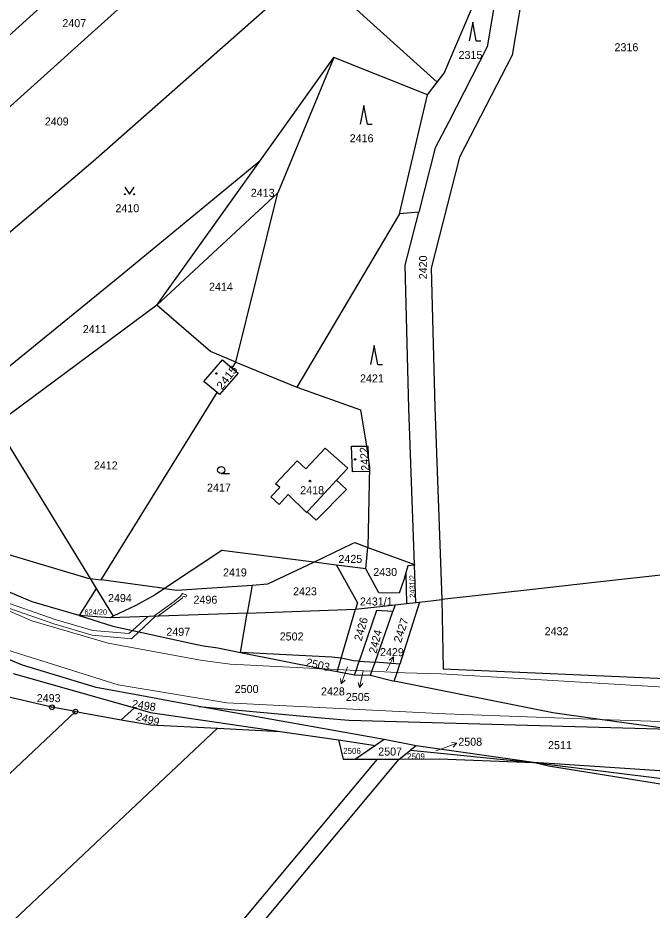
# Model space of a CAD drawing. Extents: x -606517 to -602431, y -1183120 to -1179397.
# Drawn here: x -604828.2 to -604693.5, y -1181046.7 to -1180857.3 of the extents above; entities that cross this region are included whole.
import ezdxf
from ezdxf.enums import TextEntityAlignment as Align

# ---------------------------------------------------------------- set-up
doc = ezdxf.new("R2010")
doc.units = 0
doc.header["$LTSCALE"] = 0.68
for name, color, linetype, lineweight in [('1', 7, 'Continuous', 25), ('13', 7, 'Continuous', 13), ('3', 7, 'Continuous', 25), ('4', 7, 'Continuous', 13), ('5', 7, 'Continuous', 25), ('7', 7, 'Continuous', 13), ('8', 7, 'Continuous', 25)]:
    doc.layers.add(name, color=color, linetype=linetype, lineweight=lineweight)
doc.layers.add('2', color=7, linetype='Continuous')

msp = doc.modelspace()

# ---------------------------------------------------------------- linework, layer by layer
at = {"layer": '1'}
for p, q in [((-604883.82, -1180909.45), (-604798.46, -1180832.55)), ((-604874.53, -1180916.36), (-604790.07, -1180840.29)), ((-604766.15, -1180846.54), (-604739.14, -1180870.96)), ((-604737.64, -1180869.05), (-604730.74, -1180852.82)), ((-604726.66, -1180852.57), (-604728.49, -1180863.44)), ((-604720.96, -1180851.82), (-604723.21, -1180865.2)), ((-604774.54, -1180854.61), (-604812.16, -1180887.79)), ((-604728.49, -1180863.44), (-604736.69, -1180879.34)), ((-604776.79, -1180887.7), (-604761.08, -1180865.73)), ((-604761.08, -1180865.73), (-604772.99, -1180894.46)), ((-604741.21, -1180873.62), (-604761.08, -1180865.73)), ((-604723.21, -1180865.2), (-604734.38, -1180886.88)), ((-604739.14, -1180870.96), (-604737.64, -1180869.05)), ((-604741.21, -1180873.62), (-604739.14, -1180870.96)), ((-604747.14, -1180898.88), (-604741.21, -1180873.62)), ((-604736.69, -1180879.34), (-604739.56, -1180884.92)), ((-604739.56, -1180884.92), (-604743.04, -1180898.58)), ((-604734.38, -1180886.88), (-604740.38, -1180910.45)), ((-604812.16, -1180887.79), (-604859.22, -1180927.76)), ((-604776.79, -1180887.7), (-604806.84, -1180912.52)), ((-604798.64, -1180918.27), (-604776.79, -1180887.7)), ((-604772.99, -1180894.46), (-604798.64, -1180918.27)), ((-604781.86, -1180930.38), (-604772.99, -1180894.46)), ((-604743.04, -1180898.58), (-604747.14, -1180898.88)), ((-604745.9, -1180909.83), (-604743.04, -1180898.58)), ((-604747.14, -1180898.88), (-604768.9, -1180935.67)), ((-604745.15, -1180940.14), (-604745.9, -1180909.83)), ((-604740.38, -1180910.45), (-604739.65, -1180939.97)), ((-604806.84, -1180912.52), (-604841.26, -1180940.43)), ((-604798.64, -1180918.27), (-604832.85, -1180943.64)), ((-604791.84, -1180924.16), (-604798.64, -1180918.27)), ((-604787.27, -1180928.13), (-604791.84, -1180924.16)), ((-604781.86, -1180930.38), (-604787.27, -1180928.13)), ((-604788.66, -1180934.48), (-604784.7, -1180929.92)), ((-604784.7, -1180929.92), (-604782.64, -1180931.65)), ((-604782.64, -1180931.65), (-604781.86, -1180930.38)), ((-604781.86, -1180930.38), (-604768.9, -1180935.67)), ((-604781.37, -1180932.71), (-604785.34, -1180937.28)), ((-604782.64, -1180931.65), (-604781.37, -1180932.71)), ((-604785.85, -1180936.84), (-604788.66, -1180934.48)), ((-604768.9, -1180935.67), (-604755.41, -1180940.51)), ((-604810.45, -1180976.64), (-604785.85, -1180936.84)), ((-604785.34, -1180937.28), (-604785.85, -1180936.84)), ((-604743.94, -1180973.33), (-604745.15, -1180940.14)), ((-604739.65, -1180939.97), (-604738.17, -1180980.8)), ((-604755.41, -1180940.51), (-604754.16, -1180948.23)), ((-604832.85, -1180943.64), (-604824.77, -1180956.82)), ((-604767.02, -1180953.07), (-604762.91, -1180948.65)), ((-604762.91, -1180948.65), (-604758.08, -1180952.92)), ((-604757.33, -1180948.26), (-604754.16, -1180948.23)), ((-604757.09, -1180953.71), (-604757.33, -1180948.26)), ((-604754.16, -1180948.23), (-604753.61, -1180951.66)), ((-604773.43, -1180956.25), (-604768.84, -1180951.34)), ((-604768.84, -1180951.34), (-604767.02, -1180953.07)), ((-604753.61, -1180951.66), (-604753.51, -1180953.63)), ((-604753.61, -1180951.66), (-604753.47, -1180952.51)), ((-604758.08, -1180952.92), (-604760.47, -1180955.48)), ((-604753.47, -1180952.51), (-604753.86, -1180969.72)), ((-604753.51, -1180953.63), (-604757.09, -1180953.71)), ((-604824.77, -1180956.82), (-604812.82, -1180976.31)), ((-604774.41, -1180959.01), (-604772.56, -1180956.98)), ((-604772.56, -1180956.98), (-604773.43, -1180956.25)), ((-604760.47, -1180955.48), (-604758.39, -1180957.42)), ((-604772.65, -1180960.61), (-604774.41, -1180959.01)), ((-604770.77, -1180958.47), (-604772.65, -1180960.61)), ((-604766.86, -1180962.3), (-604770.77, -1180958.47)), ((-604758.39, -1180957.42), (-604764.84, -1180963.92)), ((-604766.74, -1180962.17), (-604766.86, -1180962.3)), ((-604764.84, -1180963.92), (-604766.74, -1180962.17)), ((-604850.83, -1180965.08), (-604813.29, -1180976.25)), ((-604757.08, -1180968.92), (-604756.64, -1180968.71)), ((-604756.64, -1180968.71), (-604753.86, -1180969.72)), ((-604784.86, -1180970.41), (-604797.01, -1180978.47)), ((-604765.34, -1180972.86), (-604784.86, -1180970.41)), ((-604765.34, -1180972.86), (-604757.08, -1180968.92)), ((-604754.25, -1180974.24), (-604753.86, -1180969.72)), ((-604753.86, -1180969.72), (-604743.94, -1180973.33)), ((-604825.12, -1180981.3), (-604849.66, -1180970.95)), ((-604775.05, -1180977.48), (-604765.34, -1180972.86)), ((-604760.53, -1180973.46), (-604765.34, -1180972.86)), ((-604760.53, -1180973.46), (-604756.08, -1180981.5)), ((-604754.25, -1180974.24), (-604760.53, -1180973.46)), ((-604751.55, -1180979.33), (-604754.25, -1180974.24)), ((-604745.38, -1180973.6), (-604745.8, -1180975.12)), ((-604743.94, -1180973.47), (-604745.38, -1180973.6)), ((-604743.94, -1180973.33), (-604743.94, -1180973.47)), ((-604743.65, -1180981.41), (-604743.94, -1180973.47)), ((-604813.29, -1180976.25), (-604812.82, -1180976.31)), ((-604812.82, -1180976.31), (-604811.54, -1180978.41)), ((-604812.82, -1180976.31), (-604810.45, -1180976.64)), ((-604745.8, -1180975.12), (-604746.2, -1180976.57)), ((-604745.8, -1180975.12), (-604745.67, -1180981.63)), ((-604683.82, -1180974.75), (-604705.76, -1180977.19)), ((-604797.01, -1180978.47), (-604810.45, -1180976.64)), ((-604794.43, -1180978.82), (-604778.43, -1180977.72)), ((-604778.43, -1180977.72), (-604779.45, -1180983.66)), ((-604778.43, -1180977.72), (-604775.05, -1180977.48)), ((-604746.2, -1180976.57), (-604747.2, -1180979.43)), ((-604705.76, -1180977.19), (-604719.45, -1180978.72)), ((-604811.54, -1180978.41), (-604815.12, -1180984.19)), ((-604811.54, -1180978.41), (-604807.91, -1180984.33)), ((-604799.01, -1180979.76), (-604803.11, -1180982.03)), ((-604797.01, -1180978.47), (-604799.01, -1180979.76)), ((-604797.01, -1180978.47), (-604794.43, -1180978.82)), ((-604747.2, -1180979.43), (-604751.55, -1180979.33)), ((-604719.45, -1180978.72), (-604738.17, -1180980.8)), ((-604815.12, -1180984.19), (-604825.12, -1180981.3)), ((-604756.08, -1180981.5), (-604756.47, -1180982.84)), ((-604756.47, -1180982.84), (-604748.06, -1180981.9)), ((-604748.06, -1180981.9), (-604748.56, -1180983.34)), ((-604748.06, -1180981.9), (-604745.67, -1180981.63)), ((-604742.89, -1180981.33), (-604747.09, -1180994.5)), ((-604745.67, -1180981.63), (-604743.65, -1180981.41)), ((-604743.65, -1180981.41), (-604742.89, -1180981.33)), ((-604742.89, -1180981.33), (-604738.17, -1180980.8)), ((-604738.17, -1180980.8), (-604737.86, -1180995.52)), ((-604779.45, -1180983.66), (-604808.56, -1180984.66)), ((-604803.11, -1180982.03), (-604807.91, -1180984.33)), ((-604780.88, -1180992), (-604779.45, -1180983.66)), ((-604779.45, -1180983.66), (-604756.47, -1180982.84)), ((-604759.51, -1180993.24), (-604756.47, -1180982.84)), ((-604752.03, -1180983.14), (-604755.67, -1180993.88)), ((-604752.33, -1180994.12), (-604748.56, -1180983.34)), ((-604748.56, -1180983.34), (-604752.03, -1180983.14)), ((-604827.14, -1180994.71), (-604850.17, -1180985.22)), ((-604808.56, -1180984.66), (-604815.12, -1180984.19)), ((-604815.12, -1180984.19), (-604807.96, -1180986.45)), ((-604807.91, -1180984.33), (-604808.56, -1180984.66)), ((-604807.96, -1180986.45), (-604790.18, -1180990.33)), ((-604790.18, -1180990.33), (-604788.74, -1180990.64)), ((-604788.74, -1180990.64), (-604785.7, -1180991.04)), ((-604785.7, -1180991.04), (-604780.88, -1180992)), ((-604780.88, -1180992), (-604763.39, -1180995.47)), ((-604761.51, -1180993.05), (-604780.88, -1180992)), ((-604759.51, -1180993.24), (-604761.51, -1180993.05)), ((-604760.21, -1180995.62), (-604759.51, -1180993.24)), ((-604756.89, -1180993.79), (-604759.51, -1180993.24)), ((-604811.54, -1180999.47), (-604827.14, -1180994.71)), ((-604755.67, -1180993.88), (-604756.89, -1180993.79)), ((-604756.33, -1180995.82), (-604755.67, -1180993.88)), ((-604755.67, -1180993.88), (-604752.33, -1180994.12)), ((-604752.99, -1180995.98), (-604752.33, -1180994.12)), ((-604747.09, -1180994.5), (-604752.33, -1180994.12)), ((-604747.64, -1180996.25), (-604747.09, -1180994.5)), ((-604829.17, -1180996.48), (-604803.37, -1181003.79)), ((-604763.39, -1180995.47), (-604760.34, -1180996.07)), ((-604760.34, -1180996.07), (-604760.21, -1180995.62)), ((-604760.34, -1180996.07), (-604756.66, -1180996.78)), ((-604756.66, -1180996.78), (-604756.33, -1180995.82)), ((-604756.66, -1180996.78), (-604753.28, -1180996.82)), ((-604753.28, -1180996.82), (-604752.99, -1180995.98)), ((-604753.28, -1180996.82), (-604748.23, -1180998.09)), ((-604737.86, -1180995.52), (-604687.05, -1180997.74)), ((-604820.91, -1181003.67), (-604833.9, -1181000.64)), ((-604800.73, -1181001.48), (-604811.54, -1180999.47)), ((-604789.72, -1181003.5), (-604800.73, -1181001.48)), ((-604953.33, -1181133.92), (-604815.93, -1181004.56)), ((-604815.93, -1181004.56), (-604820.91, -1181003.67)), ((-604815.93, -1181004.56), (-604806.23, -1181006.3)), ((-604803.37, -1181003.79), (-604806.23, -1181006.3)), ((-604803.37, -1181003.79), (-604799.97, -1181004.75)), ((-604789.72, -1181003.5), (-604762.89, -1181005.97)), ((-604750.38, -1181010.51), (-604789.72, -1181003.5)), ((-604806.23, -1181006.3), (-604800.01, -1181007.41)), ((-604799.97, -1181004.75), (-604772.49, -1181008.78)), ((-604762.89, -1181005.97), (-604757.91, -1181006.4)), ((-604757.91, -1181006.4), (-604689.62, -1181008.3)), ((-604704.6, -1181006.23), (-604714.61, -1181004.84)), ((-604689.62, -1181008.3), (-604704.6, -1181006.23)), ((-604785.78, -1181008.12), (-604923.13, -1181137.43)), ((-604800.01, -1181007.41), (-604785.78, -1181008.12)), ((-604785.78, -1181008.12), (-604772.49, -1181008.78)), ((-604772.49, -1181008.78), (-604760.05, -1181010.6)), ((-604760.05, -1181010.6), (-604759.12, -1181014.69)), ((-604760.05, -1181010.6), (-604752.19, -1181011.75)), ((-604752.19, -1181011.75), (-604756.5, -1181014.69)), ((-604750.38, -1181010.51), (-604752.19, -1181011.75)), ((-604743.61, -1181011.86), (-604750.38, -1181010.51)), ((-604743.61, -1181011.86), (-604744.77, -1181012.75)), ((-604718.65, -1181015.41), (-604743.61, -1181011.86)), ((-604747.23, -1181014.65), (-604744.77, -1181012.75)), ((-604744.77, -1181012.75), (-604718.65, -1181015.41)), ((-604751.9, -1181014.67), (-604793.54, -1181064.57)), ((-604791.14, -1181067.3), (-604747.23, -1181014.65)), ((-604759.12, -1181014.69), (-604756.5, -1181014.69)), ((-604756.5, -1181014.69), (-604751.9, -1181014.67)), ((-604751.9, -1181014.67), (-604747.23, -1181014.65)), ((-604747.23, -1181014.65), (-604738.69, -1181014.62)), ((-604738.69, -1181014.62), (-604718.65, -1181015.41)), ((-604718.65, -1181015.41), (-604682.87, -1181019.82)), ((-604715.53, -1181016.18), (-604718.65, -1181015.41)), ((-604714.22, -1181015.7), (-604718.65, -1181015.41)), ((-604683.36, -1181021.34), (-604715.53, -1181016.18))]:
    msp.add_line(p, q, dxfattribs=at)
for points in [[(-604714.61, -1181004.84), (-604748.23, -1180998.09), (-604747.64, -1180996.25)], [(-604682.87, -1181019.82), (-604682.24, -1181017.81), (-604714.22, -1181015.7)]]:
    msp.add_lwpolyline(points, dxfattribs=at)
at = {"layer": '13'}
for points in [[(-604798.44, -1180984.31), (-604794.69, -1180981.57), (-604793.3, -1180980.47), (-604793.03, -1180980.1), (-604792.49, -1180980.31), (-604792.31, -1180979.85), (-604793.19, -1180979.5), (-604793.66, -1180980.11), (-604794.99, -1180981.17), (-604799.32, -1180984.34)], [(-604800.54, -1180984.38), (-604803.82, -1180987.35), (-604802.49, -1180987.64), (-604798.93, -1180984.33)]]:
    msp.add_lwpolyline(points, close=True, dxfattribs=at)
msp.add_lwpolyline([(-604833.19, -1180981.53), (-604820.51, -1180985.97), (-604812.4, -1180988.33), (-604804.06, -1180989.1), (-604802.49, -1180987.64), (-604803.82, -1180987.35), (-604804.56, -1180988.03), (-604812.2, -1180987.35), (-604820.21, -1180985.01), (-604832.81, -1180980.61)], dxfattribs=at)
at = {"layer": '3'}
for p, q in [((-604730.84, -1180862.19), (-604729.844, -1180862.19)), ((-604753.95, -1180879.88), (-604752.954, -1180879.88)), ((-604751.76, -1180930.86), (-604750.764, -1180930.86)), ((-604784.983, -1180954.05), (-604783.233, -1180954.05))]:
    msp.add_line(p, q, dxfattribs=at)
for points in [[(-604730.84, -1180862.19), (-604731.59, -1180858.19), (-604732.34, -1180862.19)], [(-604753.95, -1180879.88), (-604754.7, -1180875.88), (-604755.45, -1180879.88)], [(-604805.44, -1180893.239), (-604804.44, -1180894.74), (-604803.44, -1180893.239)], [(-604751.76, -1180930.86), (-604752.51, -1180926.86), (-604753.26, -1180930.86)]]:
    msp.add_lwpolyline(points, dxfattribs=at)
for centre, radius in [((-604805.44, -1180894.7395), 0.1), ((-604803.44, -1180894.7395), 0.1), ((-604784.9829, -1180953.2998), 0.75)]:
    msp.add_circle(centre, radius, dxfattribs=at)
at = {"layer": '4'}
for p, q in [((-604754.16, -1180948.23), (-604753.77, -1180948.22)), ((-604753.77, -1180948.22), (-604753.61, -1180951.66)), ((-604851.38, -1180973.89), (-604825.21, -1180985.29)), ((-604783.07, -1180994.49), (-604789.36, -1180993.65)), ((-604737.36, -1181005.03), (-604704.6, -1181006.23)), ((-604704.6, -1181006.23), (-604689.42, -1181006.78))]:
    msp.add_line(p, q, dxfattribs=at)
for points in [[(-604760.47, -1180955.48), (-604766.45, -1180961.86), (-604766.74, -1180962.17)], [(-604825.21, -1180985.29), (-604808.98, -1180990.07), (-604789.36, -1180993.65)], [(-604830.49, -1180991.47), (-604806.89, -1180998.93), (-604783.79, -1181002.75), (-604737.36, -1181005.03)], [(-604760.21, -1180995.62), (-604763.39, -1180995.47), (-604783.07, -1180994.49)], [(-604745.98, -1180996.33), (-604747.64, -1180996.25), (-604752.99, -1180995.98), (-604756.33, -1180995.82), (-604760.21, -1180995.62)], [(-604687.32, -1180999.57), (-604738.35, -1180996.57), (-604745.98, -1180996.33)]]:
    msp.add_lwpolyline(points, dxfattribs=at)
at = {"layer": '5'}
for centre in [(-604786.0268, -1180932.7992), (-604756.5768, -1180951.0392), (-604766.1168, -1180955.6492)]:
    msp.add_circle(centre, 0.175, dxfattribs=at)
at = {"layer": '7'}
for p, q in [((-604748.398, -1180992.986), (-604749.298, -1180993.651)), ((-604759.506, -1180998.65), (-604758.693, -1180997.88)), ((-604755.655, -1180999.484), (-604754.942, -1180998.621)), ((-604734.95, -1181011.284), (-604736.062, -1181011.156))]:
    msp.add_line(p, q, dxfattribs=at)
for points in [[(-604749.9, -1180995.93), (-604749.76, -1180995.66), (-604748.398, -1180992.986), (-604748.406, -1180994.106)], [(-604758.2, -1180995.07), (-604758.48, -1180995.83), (-604759.506, -1180998.65), (-604759.634, -1180997.538)], [(-604754.84, -1180995.93), (-604754.98, -1180996.56), (-604755.655, -1180999.484), (-604755.918, -1180998.396)], [(-604739.45, -1181012.93), (-604737.77, -1181012.31), (-604734.95, -1181011.284), (-604735.72, -1181012.097)]]:
    msp.add_lwpolyline(points, dxfattribs=at)
at = {"layer": '8'}
for centre, radius in [((-604820.91, -1181003.6699), 0.5), ((-604820.91, -1181003.6699), 0.0303), ((-604815.93, -1181004.5599), 0.5), ((-604815.93, -1181004.5599), 0.0303)]:
    msp.add_circle(centre, radius, dxfattribs=at)

# ---------------------------------------------------------------- texts
at = {"layer": '2'}
for s, height, p in [('2407', 1.7, (-604818.7, -1180859.265)), ('2316', 1.7, (-604701.48, -1180864.375)), ('2315', 1.7, (-604734.59, -1180866.015)), ('2409', 1.7, (-604822.43, -1180880.135)), ('2416', 1.7, (-604757.7, -1180883.705)), ('2413', 1.7, (-604778.7, -1180895.285)), ('2410', 1.7, (-604807.44, -1180898.565)), ('2414', 1.7, (-604787.57, -1180915.225)), ('2411', 1.7, (-604814.36, -1180924.235)), ('2421', 1.7, (-604755.51, -1180934.685)), ('2412', 1.7, (-604812.01, -1180953.165)), ('2417', 1.7, (-604787.99, -1180957.875)), ('2418', 1.7, (-604768.2, -1180958.425)), ('2425', 1.7, (-604760.1, -1180973.015)), ('2419', 1.7, (-604784.6, -1180975.885)), ('2430', 1.7, (-604752.7, -1180975.795)), ('2423', 1.7, (-604769.73, -1180979.895)), ('2494', 1.7, (-604809.02, -1180981.325)), ('2496', 1.7, (-604790.86, -1180981.675)), ('2497', 1.7, (-604796.63, -1180988.485)), ('2432', 1.7, (-604716.31, -1180988.365)), ('2502', 1.7, (-604772.56, -1180989.475)), ('2429', 1.7, (-604751.27, -1180992.805)), ('2500', 1.7, (-604782.11, -1181000.635)), ('2493', 1.7, (-604824.14, -1181002.565)), ('2428', 1.7, (-604763.8, -1181001.145)), ('2505', 1.7, (-604758.52, -1181002.335)), ('2508', 1.7, (-604734.64, -1181011.835)), ('2506', 1.27, (-604759.1, -1181013.557)), ('2507', 1.7, (-604751.65, -1181013.915)), ('2511', 1.7, (-604715.59, -1181012.545)), ('2509', 1.27, (-604745.52, -1181014.727))]:
    msp.add_text(s, height=height, dxfattribs=at).set_placement(p)
for s, rotation, p in [('2420', 90, (-604741.265, -1180912.8)), ('2422', 94, (-604753.536, -1180953.39)), ('2426', 74, (-604755.191, -1180989.727)), ('2424', 76, (-604752.037, -1180992.372)), ('2503', 347, (-604767.105, -1180994.884)), ('2498', 351, (-604804.016, -1181003.689)), ('2499', 344, (-604803.237, -1181006.298))]:
    msp.add_text(s, height=1.7, rotation=rotation, dxfattribs=at).set_placement(p)
for s, rotation, width, p in [('2415', 52, 1.1, (-604784.815, -1180936.381)), ('2427', 72, 1.05, (-604746.825, -1180990.091))]:
    msp.add_text(s, height=1.7, rotation=rotation, dxfattribs=dict(at, width=width)).set_placement(p)
msp.add_text('2431/2', height=1.14, rotation=91, dxfattribs=at).set_placement((-604743.8597, -1180977.9999), align=Align.CENTER)
for s, height, p in [('2431/1', 1.7, (-604752.06, -1180982.052)), ('624/20', 1.14, (-604811.609, -1180984.02))]:
    msp.add_text(s, height=height, dxfattribs=at).set_placement(p, align=Align.CENTER)

doc.saveas('drawing.dxf')
